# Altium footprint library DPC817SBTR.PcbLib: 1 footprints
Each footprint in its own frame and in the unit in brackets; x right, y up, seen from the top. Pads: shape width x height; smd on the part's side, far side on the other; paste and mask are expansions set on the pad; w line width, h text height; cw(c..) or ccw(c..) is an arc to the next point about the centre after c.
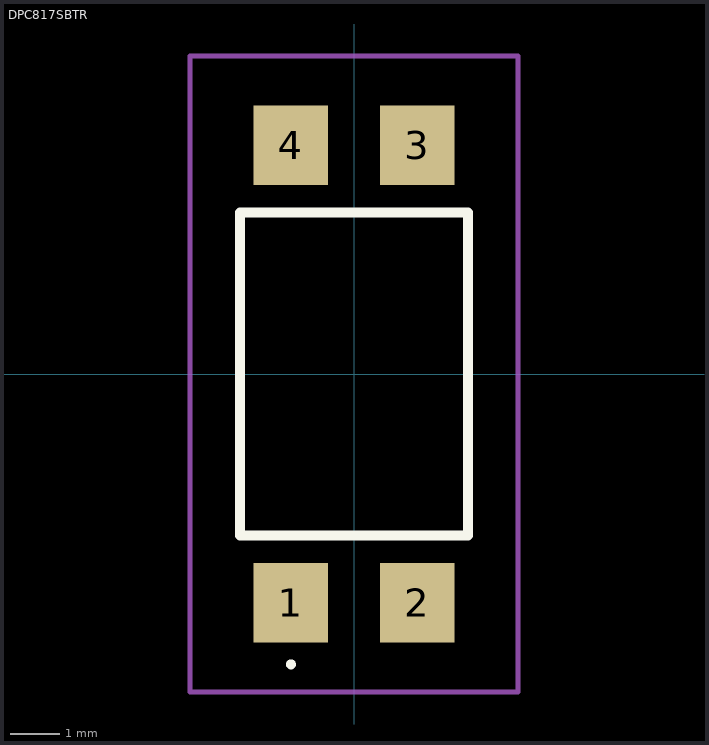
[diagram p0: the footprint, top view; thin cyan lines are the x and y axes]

## DPC817SBTR [mm]
pads (4):
  rect 1.5x1.6 smd: 1(-1.27,-4.61) 2(1.27,-4.61) 3(1.27,4.61) 4(-1.27,4.61)
Top Overlay:
  lines w0.1: -1.27,-5.9 -1.27,-5.9 ; -1.27,-5.9 ccw(c-1.27,-5.85) -1.27,-5.8 ; -1.27,-5.9 cw(c-1.27,-5.85) -1.27,-5.8 ; -1.27,-5.9 -1.27,-5.9 ; -1.27,-5.9 ccw(c-1.27,-5.85) -1.27,-5.8 ; -1.27,-5.8 -1.27,-5.8
  lines w0.2: -2.3,-3.25 -2.3,3.25 2.3,3.25 2.3,-3.25 -2.3,-3.25
Mechanical 15:
  lines w0.1: -2.3,-3.25 2.3,-3.25 2.3,3.25 -2.3,3.25 -2.3,-3.25
Mechanical 20:
  lines w0.1: -3.3,-6.41 3.3,-6.41 3.3,6.41 -3.3,6.41 -3.3,-6.41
